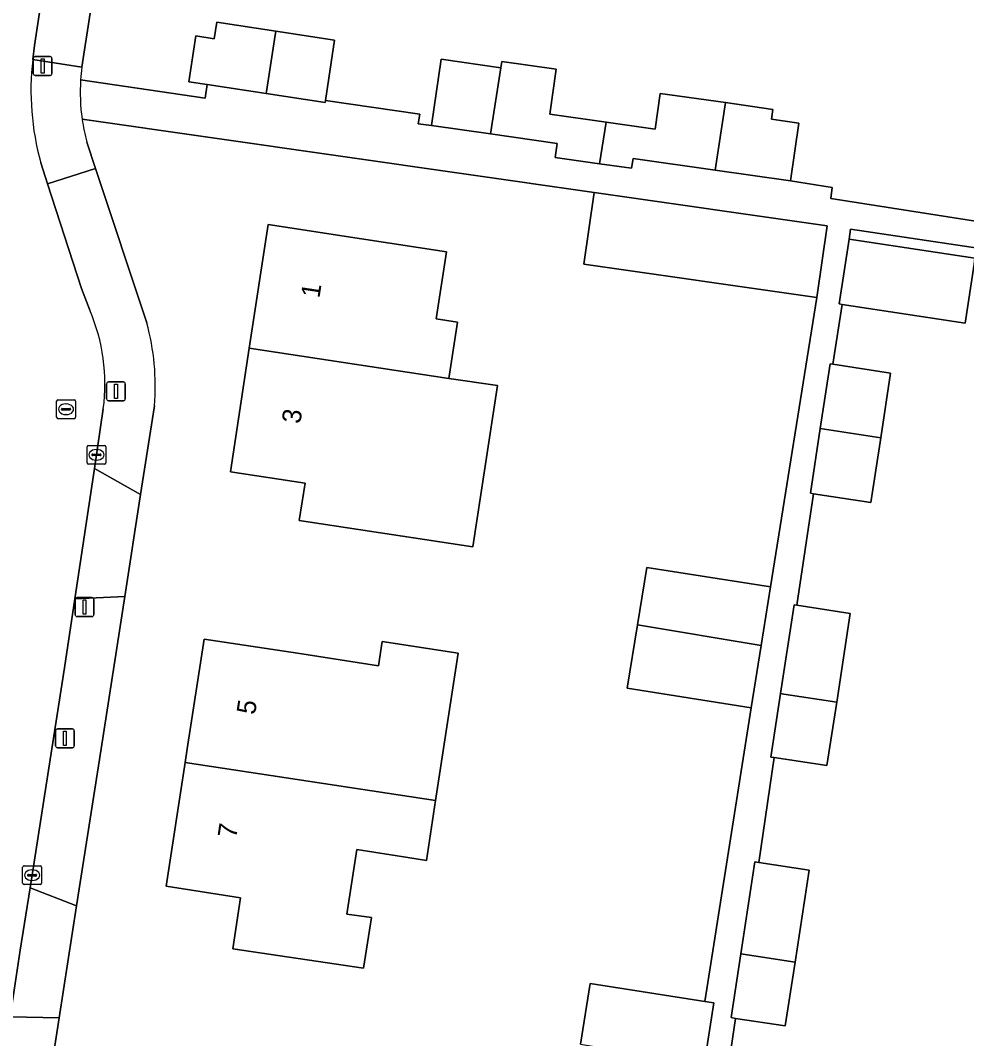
# Model space of a CAD drawing. Extents: x 161483 to 162250, y 379484 to 380833.
# Drawn here: x 161752.7 to 161802.8, y 380484.6 to 380538.6 of the extents above; entities that cross this region are included whole.
import ezdxf

# ---------------------------------------------------------------- set-up
doc = ezdxf.new("R2010")
doc.units = 0
for name, color, linetype in [('IMGEO_Erf', 7, 'Continuous'), ('IMGEO_Kolk', 7, 'Continuous'), ('IMGEO_Lichtmast', 7, 'Continuous'), ('IMGEO_Openbare_ruimte_label', 7, 'Continuous'), ('IMGEO_Pand', 7, 'Continuous'), ('IMGEO_Pand_nummerreeks', 7, 'Continuous'), ('IMGEO_Rijbaan_lokaal_open', 7, 'Continuous'), ('IMGEO_Rioolput', 7, 'Continuous'), ('IMGEO_Voetpad_open', 7, 'Continuous')]:
    doc.layers.add(name, color=color, linetype=linetype)

msp = doc.modelspace()

# ---------------------------------------------------------------- linework, layer by layer
at = {"layer": 'IMGEO_Erf'}
for points in [[(161759.824, 380561.171), (161755.969, 380536.089)], [(161755.903, 380535.427), (161762.496, 380534.451), (161762.608, 380535.177), (161761.635, 380535.327), (161762.009, 380537.755), (161762.982, 380537.605), (161763.116, 380538.478), (161766.239, 380537.998), (161769.357, 380537.519), (161768.865, 380534.324), (161773.862, 380533.615), (161773.789, 380533.101), (161774.492, 380533.001), (161774.991, 380536.514), (161778.162, 380536.064), (161778.215, 380536.403), (161781.092, 380535.995), (161780.753, 380533.606), (161783.731, 380533.183), (161786.329, 380532.814), (161786.598, 380534.708), (161790.062, 380534.216), (161792.568, 380533.86), (161792.494, 380533.34), (161793.936, 380533.135), (161793.5, 380530.07), (161795.706, 380529.72), (161795.641, 380529.132), (161805.097, 380527.662)], [(161785.887, 380509.598), (161792.446, 380508.566), (161794.9, 380523.895), (161782.555, 380525.661), (161783.099, 380529.46), (161755.982, 380533.338)], [(161756.228, 380532.132), (161756.696, 380530.722), (161759.405, 380522.557)], [(161829.598, 380522.608), (161796.688, 380527.509), (161796.61, 380526.995), (161803.27, 380525.979)], [(161803.223, 380525.671), (161802.745, 380522.54), (161796.244, 380523.531), (161795.737, 380520.359), (161798.804, 380519.891), (161798.282, 380516.465), (161797.759, 380513.038), (161794.717, 380513.503), (161793.839, 380507.593), (161796.665, 380507.162), (161795.948, 380502.462), (161795.435, 380499.101), (161792.641, 380499.527), (161791.816, 380493.969), (161794.485, 380493.561), (161793.744, 380488.702), (161793.227, 380485.315), (161790.59, 380485.718), (161789.683, 380479.612)], [(161759.811, 380518.166), (161759.08, 380513.468), (161758.238, 380508.054), (161756.985, 380500), (161755.69, 380491.68), (161754.766, 380485.737), (161752.696, 380472.423), (161752.305, 380469.908), (161748.912, 380448.084)], [(161782.371, 380484.342), (161782.89, 380487.57), (161788.971, 380486.613), (161791.418, 380502.168), (161784.859, 380503.2), (161785.398, 380506.557), (161785.887, 380509.598)]]:
    msp.add_lwpolyline(points, dxfattribs=at)
for points in [[(161776.678, 380510.684), (161767.485, 380512.086), (161767.787, 380514.064), (161763.832, 380514.667), (161764.831, 380521.215), (161765.831, 380527.763), (161770.774, 380527.008), (161775.277, 380526.321), (161774.735, 380522.765), (161775.864, 380522.593), (161775.407, 380519.6), (161777.983, 380519.238)], [(161774.221, 380494.085), (161773.225, 380494.238), (161770.529, 380494.653), (161769.999, 380491.234), (161771.312, 380491.052), (161770.887, 380488.376), (161763.965, 380489.408), (161764.368, 380492.107), (161760.441, 380492.716), (161761.439, 380499.26), (161761.552, 380500), (161762.438, 380505.807), (161767.381, 380505.053), (161771.681, 380504.396), (161771.876, 380505.672), (161775.899, 380505.058), (161774.707, 380497.248)]]:
    msp.add_lwpolyline(points, close=True, dxfattribs=at)
for centre, radius, start, end in [((161766.782, 380534.677), 10.905, 172.5585, 176.0545), ((161765.652, 380534.682), 9.763, 187.9149, 195.1431), ((161747.279, 380519.222), 12.576, 355.1854, 15.3799)]:
    msp.add_arc(centre, radius, start, end, dxfattribs=at)
at = {"layer": 'IMGEO_Kolk'}
for p, q in [((161756.24, 380515.137), (161756.24, 380515.989)), ((161756.315, 380516.063), (161757.167, 380516.063)), ((161756.728, 380515.843), (161756.753, 380515.843)), ((161757.241, 380515.989), (161757.241, 380515.137)), ((161756.499, 380515.557), (161756.499, 380515.569)), ((161756.937, 380515.52), (161756.539, 380515.52)), ((161756.542, 380515.606), (161756.94, 380515.606)), ((161756.751, 380515.283), (161756.726, 380515.283)), ((161756.983, 380515.569), (161756.983, 380515.557)), ((161757.167, 380515.063), (161756.315, 380515.063)), ((161752.832, 380492.873), (161752.832, 380493.725)), ((161752.907, 380493.799), (161753.759, 380493.799)), ((161753.833, 380493.725), (161753.833, 380492.873)), ((161753.091, 380493.293), (161753.091, 380493.305)), ((161753.529, 380493.256), (161753.131, 380493.256)), ((161753.134, 380493.342), (161753.532, 380493.342)), ((161753.32, 380493.579), (161753.345, 380493.579)), ((161753.575, 380493.305), (161753.575, 380493.293)), ((161753.759, 380492.799), (161752.907, 380492.799)), ((161753.343, 380493.019), (161753.318, 380493.019))]:
    msp.add_line(p, q, dxfattribs=at)
for points in [[(161756.24, 380515.137), (161756.24, 380515.989)], [(161756.315, 380516.063), (161757.167, 380516.063)], [(161757.241, 380515.989), (161757.241, 380515.137)], [(161757.167, 380515.063), (161756.315, 380515.063)], [(161752.832, 380492.873), (161752.832, 380493.725)], [(161752.907, 380493.799), (161753.759, 380493.799)], [(161753.833, 380493.725), (161753.833, 380492.873)], [(161753.759, 380492.799), (161752.907, 380492.799)]]:
    msp.add_lwpolyline(points, dxfattribs=at)
for centre, radius, start, end in [((161756.317, 380515.987), 0.0765, 91.552, 178.448), ((161756.317, 380515.987), 0.0765, 91.552, 178.448), ((161757.165, 380515.987), 0.0765, 1.552, 88.448), ((161757.165, 380515.987), 0.0765, 1.552, 88.448), ((161756.539, 380515.566), 0.0403, 85.8775, 175.7526), ((161756.536, 380515.556), 0.0366, 178.938, 274.7102), ((161756.94, 380515.563), 0.043, 264.8664, 352.4533), ((161756.944, 380515.568), 0.0386, 1.7309, 96.639), ((161756.317, 380515.139), 0.0765, 181.552, 268.448), ((161756.317, 380515.139), 0.0765, 181.552, 268.448), ((161757.165, 380515.139), 0.0765, 271.552, 358.448), ((161757.165, 380515.139), 0.0765, 271.552, 358.448), ((161752.909, 380493.723), 0.0765, 91.552, 178.448), ((161752.909, 380493.723), 0.0765, 91.552, 178.448), ((161753.757, 380493.723), 0.0765, 1.552, 88.448), ((161753.757, 380493.723), 0.0765, 1.552, 88.448), ((161753.131, 380493.302), 0.0403, 85.8775, 175.7526), ((161753.128, 380493.292), 0.0366, 178.938, 274.7102), ((161753.532, 380493.299), 0.043, 264.8664, 352.4533), ((161753.536, 380493.304), 0.0386, 1.7309, 96.639), ((161752.909, 380492.875), 0.0765, 181.552, 268.448), ((161752.909, 380492.875), 0.0765, 181.552, 268.448), ((161753.757, 380492.875), 0.0765, 271.552, 358.448), ((161753.757, 380492.875), 0.0765, 271.552, 358.448)]:
    msp.add_arc(centre, radius, start, end, dxfattribs=at)
for centre, major_axis, ratio, start_param, end_param in [((161756.727, 380515.563), (-0.387, 0.002), 0.722429, 4.712389, 7.853982), ((161756.752, 380515.563), (-0.39, 0.002), 0.717154, 1.570796, 4.712389), ((161753.319, 380493.299), (-0.387, 0.002), 0.722429, 4.712389, 7.853982), ((161753.344, 380493.299), (-0.39, 0.002), 0.717154, 1.570796, 4.712389)]:
    msp.add_ellipse(centre, major_axis=major_axis, ratio=ratio, start_param=start_param, end_param=end_param, dxfattribs=at)
at = {"layer": 'IMGEO_Lichtmast'}
for p, q in [((161753.395, 380535.756), (161753.395, 380536.556)), ((161753.395, 380536.556), (161753.395, 380535.756)), ((161753.495, 380536.656), (161754.285, 380536.656)), ((161754.285, 380536.656), (161753.495, 380536.656)), ((161754.385, 380536.556), (161754.385, 380535.756)), ((161754.385, 380535.756), (161754.385, 380536.556)), ((161754.285, 380535.656), (161753.495, 380535.656)), ((161753.495, 380535.656), (161754.285, 380535.656)), ((161757.278, 380518.529), (161757.278, 380519.329)), ((161757.278, 380519.329), (161757.278, 380518.529)), ((161757.378, 380519.429), (161758.168, 380519.429)), ((161758.168, 380519.429), (161757.378, 380519.429)), ((161758.268, 380519.329), (161758.268, 380518.529)), ((161758.268, 380518.529), (161758.268, 380519.329)), ((161758.168, 380518.429), (161757.378, 380518.429)), ((161757.378, 380518.429), (161758.168, 380518.429)), ((161755.612, 380507.102), (161755.612, 380507.902)), ((161755.612, 380507.902), (161755.612, 380507.102)), ((161755.712, 380508.002), (161756.502, 380508.002)), ((161756.502, 380508.002), (161755.712, 380508.002)), ((161756.602, 380507.902), (161756.602, 380507.102)), ((161756.602, 380507.102), (161756.602, 380507.902)), ((161756.502, 380507.002), (161755.712, 380507.002)), ((161755.712, 380507.002), (161756.502, 380507.002)), ((161754.575, 380500.147), (161754.575, 380500.947)), ((161754.575, 380500.947), (161754.575, 380500.147)), ((161754.675, 380501.047), (161755.465, 380501.047)), ((161755.465, 380501.047), (161754.675, 380501.047)), ((161755.565, 380500.947), (161755.565, 380500.147)), ((161755.565, 380500.147), (161755.565, 380500.947)), ((161755.465, 380500.047), (161754.675, 380500.047)), ((161754.675, 380500.047), (161755.465, 380500.047))]:
    msp.add_line(p, q, dxfattribs=at)
for points in [[(161753.815, 380536.531), (161753.965, 380536.531), (161753.965, 380535.781), (161753.815, 380535.781), (161753.815, 380536.531)], [(161757.698, 380519.304), (161757.848, 380519.304), (161757.848, 380518.554), (161757.698, 380518.554), (161757.698, 380519.304)], [(161756.032, 380507.877), (161756.182, 380507.877), (161756.182, 380507.127), (161756.032, 380507.127), (161756.032, 380507.877)], [(161754.995, 380500.922), (161755.145, 380500.922), (161755.145, 380500.172), (161754.995, 380500.172), (161754.995, 380500.922)]]:
    msp.add_lwpolyline(points, dxfattribs=at)
for centre, start, end in [((161753.495, 380536.556), 90, 180), ((161753.495, 380536.556), 90, 180), ((161754.285, 380536.556), 0, 90), ((161754.285, 380536.556), 360, 90), ((161753.495, 380535.756), 180, 270), ((161753.495, 380535.756), 180, 270), ((161754.285, 380535.756), 270, 0), ((161754.285, 380535.756), 270, 0), ((161757.378, 380519.329), 90, 180), ((161757.378, 380519.329), 90, 180), ((161758.168, 380519.329), 0, 90), ((161758.168, 380519.329), 360, 90), ((161757.378, 380518.529), 180, 270), ((161757.378, 380518.529), 180, 270), ((161758.168, 380518.529), 270, 0), ((161758.168, 380518.529), 270, 0), ((161755.712, 380507.902), 90, 180), ((161755.712, 380507.902), 90, 180), ((161756.502, 380507.902), 0, 90), ((161756.502, 380507.902), 360, 90), ((161755.712, 380507.102), 180, 270), ((161755.712, 380507.102), 180, 270), ((161756.502, 380507.102), 270, 0), ((161756.502, 380507.102), 270, 0), ((161754.675, 380500.947), 90, 180), ((161754.675, 380500.947), 90, 180), ((161755.465, 380500.947), 0, 90), ((161755.465, 380500.947), 360, 90), ((161754.675, 380500.147), 180, 270), ((161754.675, 380500.147), 180, 270), ((161755.465, 380500.147), 270, 0), ((161755.465, 380500.147), 270, 0)]:
    msp.add_arc(centre, 0.1, start, end, dxfattribs=at)
at = {"layer": 'IMGEO_Pand'}
for points in [[(161766.239, 380537.998), (161763.116, 380538.478), (161762.982, 380537.605), (161762.009, 380537.755), (161761.635, 380535.327), (161762.608, 380535.177), (161765.727, 380534.697), (161765.744, 380534.804), (161766.172, 380537.562)], [(161766.239, 380537.998), (161766.172, 380537.562), (161765.744, 380534.804), (161765.727, 380534.697), (161768.848, 380534.217), (161768.865, 380534.324), (161769.357, 380537.519)], [(161778.162, 380536.064), (161774.991, 380536.514), (161774.492, 380533.001), (161777.619, 380532.557)], [(161780.753, 380533.606), (161781.092, 380535.995), (161778.215, 380536.403), (161778.162, 380536.064), (161777.619, 380532.557), (161781.141, 380532.057), (161781.036, 380531.314), (161783.389, 380530.98), (161783.731, 380533.183)], [(161783.731, 380533.183), (161783.389, 380530.98), (161785.086, 380530.739), (161785.16, 380531.255), (161789.506, 380530.637), (161790.062, 380534.216), (161786.598, 380534.708), (161786.329, 380532.814)], [(161789.506, 380530.637), (161793.5, 380530.07), (161793.936, 380533.135), (161792.494, 380533.34), (161792.568, 380533.86), (161790.062, 380534.216)], [(161783.099, 380529.46), (161782.555, 380525.661), (161794.9, 380523.895), (161795.443, 380527.694)], [(161775.407, 380519.6), (161775.864, 380522.593), (161774.735, 380522.765), (161775.277, 380526.321), (161770.774, 380527.008), (161765.831, 380527.763), (161764.831, 380521.215)], [(161803.223, 380525.671), (161803.27, 380525.979), (161796.61, 380526.995), (161796.085, 380523.555), (161796.244, 380523.531), (161802.745, 380522.54)], [(161775.407, 380519.6), (161764.831, 380521.215), (161763.832, 380514.667), (161767.787, 380514.064), (161767.485, 380512.086), (161776.678, 380510.684), (161777.983, 380519.238)], [(161795.737, 380520.359), (161795.602, 380520.38), (161795.08, 380516.953), (161798.282, 380516.465), (161798.804, 380519.891)], [(161798.282, 380516.465), (161795.08, 380516.953), (161794.557, 380513.527), (161794.717, 380513.503), (161797.759, 380513.038)], [(161791.948, 380505.466), (161792.446, 380508.566), (161785.887, 380509.598), (161785.398, 380506.557)], [(161796.665, 380507.162), (161793.839, 380507.593), (161793.697, 380507.615), (161792.98, 380502.915), (161793.14, 380502.891), (161795.948, 380502.462)], [(161791.948, 380505.466), (161785.398, 380506.557), (161784.859, 380503.2), (161791.418, 380502.168)], [(161761.439, 380499.26), (161774.707, 380497.248), (161775.899, 380505.058), (161771.876, 380505.672), (161771.681, 380504.396), (161767.381, 380505.053), (161762.438, 380505.807), (161761.552, 380500)], [(161795.948, 380502.462), (161793.14, 380502.891), (161792.98, 380502.915), (161792.467, 380499.554), (161792.641, 380499.527), (161795.435, 380499.101)], [(161761.439, 380499.26), (161760.441, 380492.716), (161764.368, 380492.107), (161763.965, 380489.408), (161770.887, 380488.376), (161771.312, 380491.052), (161769.999, 380491.234), (161770.529, 380494.653), (161773.225, 380494.238), (161774.221, 380494.085), (161774.707, 380497.248)], [(161791.816, 380493.969), (161791.611, 380494), (161790.87, 380489.141), (161793.744, 380488.702), (161794.485, 380493.561)], [(161793.744, 380488.702), (161790.87, 380489.141), (161790.353, 380485.754), (161790.59, 380485.718), (161793.227, 380485.315)], [(161789.449, 380486.538), (161788.971, 380486.613), (161782.89, 380487.57), (161782.371, 380484.342), (161788.922, 380483.26)]]:
    msp.add_lwpolyline(points, close=True, dxfattribs=at)
at = {"layer": 'IMGEO_Rijbaan_lokaal_open'}
for points in [[(161753.363, 380536.499), (161753.467, 380537.247), (161753.9, 380540.172), (161755.535, 380550.773), (161757.034, 380560.392), (161757.402, 380562.904), (161752.625, 380563.589), (161752.161, 380560.866), (161751.484, 380556.751), (161749.641, 380545.022), (161748.852, 380540.104), (161748.652, 380538.854), (161748.238, 380535.839), (161748.011, 380534.961), (161747.898, 380534.562), (161747.662, 380533.825)], [(161756.385, 380523.233), (161755.955, 380524.375), (161754.154, 380529.915), (161753.789, 380531.038)], [(161746.487, 380448.105), (161746.564, 380448.816), (161747.536, 380455.574), (161748.798, 380463.6), (161749.749, 380469.769), (161750.339, 380473.597), (161750.589, 380475.219), (161752.178, 380485.804), (161752.708, 380489.333), (161753.226, 380492.628), (161754.384, 380500), (161755.056, 380504.275), (161755.602, 380507.939), (161756.631, 380514.835), (161757.103, 380518.001)]]:
    msp.add_lwpolyline(points, dxfattribs=at)
for centre, radius, start, end in [((161767.728, 380534.872), 14.457, 173.5398, 195.3812), ((161747.198, 380519.307), 9.991, 352.4888, 23.1392)]:
    msp.add_arc(centre, radius, start, end, dxfattribs=at)
at = {"layer": 'IMGEO_Rioolput'}
for p, q in [((161754.703, 380518.478), (161755.555, 380518.478)), ((161754.628, 380517.552), (161754.628, 380518.404)), ((161754.887, 380517.972), (161754.887, 380517.984)), ((161755.325, 380517.935), (161754.927, 380517.935)), ((161754.93, 380518.021), (161755.328, 380518.021)), ((161755.116, 380518.258), (161755.141, 380518.258)), ((161755.371, 380517.984), (161755.371, 380517.972)), ((161755.629, 380518.404), (161755.629, 380517.552)), ((161755.555, 380517.478), (161754.703, 380517.478)), ((161755.139, 380517.698), (161755.114, 380517.698))]:
    msp.add_line(p, q, dxfattribs=at)
for points in [[(161754.703, 380518.478), (161755.555, 380518.478)], [(161754.628, 380517.552), (161754.628, 380518.404)], [(161755.629, 380518.404), (161755.629, 380517.552)], [(161755.555, 380517.478), (161754.703, 380517.478)]]:
    msp.add_lwpolyline(points, dxfattribs=at)
for centre, radius, start, end in [((161754.705, 380518.402), 0.0765, 91.552, 178.448), ((161754.705, 380518.402), 0.0765, 91.552, 178.448), ((161755.553, 380518.402), 0.0765, 1.552, 88.448), ((161755.553, 380518.402), 0.0765, 1.552, 88.448), ((161754.927, 380517.981), 0.0403, 85.8775, 175.7526), ((161754.924, 380517.971), 0.0366, 178.938, 274.7102), ((161755.328, 380517.978), 0.043, 264.8664, 352.4533), ((161755.332, 380517.983), 0.0386, 1.7309, 96.639), ((161754.705, 380517.554), 0.0765, 181.552, 268.448), ((161754.705, 380517.554), 0.0765, 181.552, 268.448), ((161755.553, 380517.554), 0.0765, 271.552, 358.448), ((161755.553, 380517.554), 0.0765, 271.552, 358.448)]:
    msp.add_arc(centre, radius, start, end, dxfattribs=at)
for centre, major_axis, ratio, start_param, end_param in [((161755.115, 380517.978), (-0.387, 0.002), 0.722429, 4.712389, 7.853982), ((161755.14, 380517.978), (-0.39, 0.002), 0.717154, 1.570796, 4.712389)]:
    msp.add_ellipse(centre, major_axis=major_axis, ratio=ratio, start_param=start_param, end_param=end_param, dxfattribs=at)
at = {"layer": 'IMGEO_Voetpad_open'}
for points in [[(161757.402, 380562.904), (161757.034, 380560.392), (161755.535, 380550.773), (161753.9, 380540.172), (161753.467, 380537.247), (161753.363, 380536.499), (161755.969, 380536.089), (161759.824, 380561.171)], [(161755.969, 380536.089), (161753.363, 380536.499)], [(161805.097, 380527.662), (161795.641, 380529.132), (161795.706, 380529.72), (161793.5, 380530.07), (161789.506, 380530.637), (161785.16, 380531.255), (161785.086, 380530.739), (161783.389, 380530.98), (161781.036, 380531.314), (161781.141, 380532.057), (161777.619, 380532.557), (161774.492, 380533.001), (161773.789, 380533.101), (161773.862, 380533.615), (161768.865, 380534.324), (161768.848, 380534.217), (161765.727, 380534.697), (161762.608, 380535.177), (161762.496, 380534.451), (161755.903, 380535.427)], [(161755.982, 380533.338), (161783.099, 380529.46), (161795.443, 380527.694), (161794.9, 380523.895), (161792.446, 380508.566), (161791.948, 380505.466), (161791.418, 380502.168), (161788.971, 380486.613), (161789.449, 380486.538), (161788.922, 380483.26), (161788.421, 380480.14), (161786.854, 380468.998), (161788.079, 380468.816), (161788.57, 380472.122), (161788.295, 380472.163), (161788.772, 380475.374), (161789.409, 380479.653), (161789.683, 380479.612), (161790.59, 380485.718), (161790.353, 380485.754), (161790.87, 380489.141), (161791.611, 380494), (161791.816, 380493.969), (161792.641, 380499.527)], [(161753.789, 380531.038), (161754.154, 380529.915), (161756.696, 380530.722), (161756.228, 380532.132)], [(161759.405, 380522.557), (161756.696, 380530.722), (161754.154, 380529.915), (161755.955, 380524.375), (161756.385, 380523.233)], [(161792.641, 380499.527), (161792.467, 380499.554), (161792.98, 380502.915), (161793.697, 380507.615), (161793.839, 380507.593), (161794.717, 380513.503), (161794.557, 380513.527), (161795.08, 380516.953), (161795.602, 380520.38), (161795.737, 380520.359), (161796.244, 380523.531), (161796.085, 380523.555), (161796.61, 380526.995), (161796.688, 380527.509), (161829.598, 380522.608)], [(161757.103, 380518.001), (161756.631, 380514.835), (161759.08, 380513.468), (161759.811, 380518.166)]]:
    msp.add_lwpolyline(points, dxfattribs=at)
for points in [[(161758.238, 380508.054), (161759.08, 380513.468), (161756.631, 380514.835), (161755.602, 380507.939)], [(161755.69, 380491.68), (161756.985, 380500), (161758.238, 380508.054), (161755.602, 380507.939), (161755.056, 380504.275), (161754.384, 380500), (161753.226, 380492.628)], [(161755.69, 380491.68), (161753.226, 380492.628), (161752.708, 380489.333), (161752.178, 380485.804), (161754.766, 380485.737)], [(161750.339, 380473.597), (161752.696, 380472.423), (161754.766, 380485.737), (161752.178, 380485.804), (161750.589, 380475.219)]]:
    msp.add_lwpolyline(points, close=True, dxfattribs=at)
for centre, radius, start, end in [((161767.728, 380534.872), 14.457, 173.5398, 195.3812), ((161766.782, 380534.677), 10.905, 172.5585, 176.0545), ((161765.991, 380534.763), 10.11, 176.2313, 188.1002), ((161765.991, 380534.763), 10.11, 176.2313, 188.1002), ((161765.652, 380534.682), 9.763, 187.9149, 195.1431), ((161747.198, 380519.307), 9.991, 352.4888, 23.1392), ((161747.279, 380519.222), 12.576, 355.1854, 15.3799)]:
    msp.add_arc(centre, radius, start, end, dxfattribs=at)

# ---------------------------------------------------------------- texts
at = {"layer": 'IMGEO_Openbare_ruimte_label'}
msp.add_text('Semmelweislaan', height=1, rotation=81.3105, dxfattribs=at).set_placement((161752.094, 380537.718))
at = {"layer": 'IMGEO_Pand_nummerreeks'}
for s, rotation, p in [('1', 81.3212, (161768.549, 380523.835)), ('3', 81.3212, (161767.533, 380517.174)), ('5', 81.3265, (161765.14, 380501.768)), ('7', 81.3289, (161764.141, 380495.222))]:
    msp.add_text(s, height=1, rotation=rotation, dxfattribs=at).set_placement(p)

doc.saveas('drawing.dxf')
